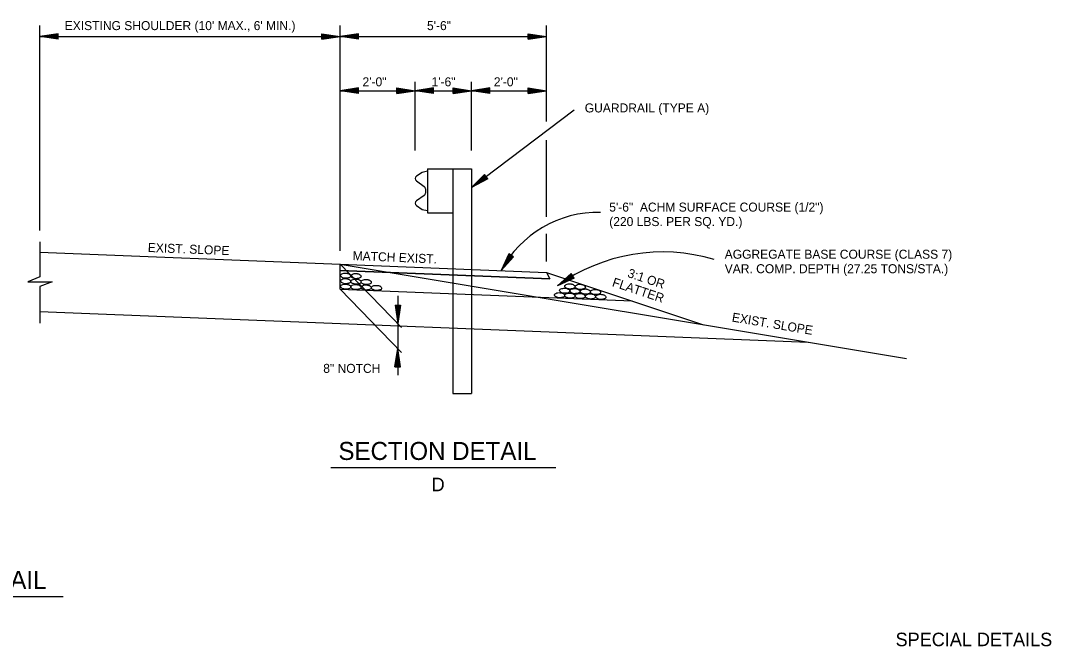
# Model space of a CAD drawing. Extents: x 1374136 to 1374281, y 380549 to 380948.
# Drawn here: x 1374212.2 to 1374280.9, y 380848.8 to 380890.4 of the extents above; entities that cross this region are included whole.
import ezdxf

# ---------------------------------------------------------------- set-up
doc = ezdxf.new("R2010")
doc.units = 0
for name, color, linetype in [('C-ANNO-TEXT', 7, 'Continuous'), ('Default', 7, 'Continuous'), ('G-ANNO-TEXT', 7, 'Continuous'), ('R_Draft', 7, 'Continuous')]:
    doc.layers.add(name, color=color, linetype=linetype)

msp = doc.modelspace()

# ---------------------------------------------------------------- linework, layer by layer
at = {"layer": 'C-ANNO-TEXT'}
msp.add_lwpolyline([(1374213.507, 380875.703), (1374213.507, 380873.373), (1374212.696, 380873.049), (1374214.318, 380873.049), (1374213.507, 380872.726), (1374213.507, 380870.301)], dxfattribs=at)
at = {"layer": 'Default'}
for p, q in [((1374213.507, 380876.461), (1374213.507, 380890.113)), ((1374214.724, 380889.571), (1374213.507, 380889.388)), ((1374214.724, 380889.54), (1374213.711, 380889.388)), ((1374214.724, 380889.508), (1374213.92, 380889.388)), ((1374214.725, 380889.204), (1374214.724, 380889.571)), ((1374232.29, 380889.571), (1374233.507, 380889.388)), ((1374232.29, 380889.204), (1374232.29, 380889.571)), ((1374232.29, 380889.54), (1374233.303, 380889.388)), ((1374232.29, 380889.508), (1374233.094, 380889.388)), ((1374233.507, 380875.114), (1374233.507, 380890.113)), ((1374234.724, 380889.571), (1374233.507, 380889.388)), ((1374234.724, 380889.54), (1374233.711, 380889.388)), ((1374234.724, 380889.508), (1374233.92, 380889.388)), ((1374234.725, 380889.204), (1374234.724, 380889.571)), ((1374246.04, 380889.571), (1374247.257, 380889.388)), ((1374246.04, 380889.204), (1374246.04, 380889.571)), ((1374246.04, 380889.54), (1374247.053, 380889.388)), ((1374246.04, 380889.508), (1374246.844, 380889.388)), ((1374247.257, 380883.73), (1374247.257, 380890.113)), ((1374213.507, 380889.388), (1374233.507, 380889.388)), ((1374214.725, 380889.204), (1374213.507, 380889.388)), ((1374214.725, 380889.236), (1374213.711, 380889.388)), ((1374214.725, 380889.267), (1374213.92, 380889.388)), ((1374214.724, 380889.479), (1374214.124, 380889.388)), ((1374214.725, 380889.297), (1374214.124, 380889.388)), ((1374214.724, 380889.447), (1374214.328, 380889.389)), ((1374214.725, 380889.328), (1374214.328, 380889.389)), ((1374214.725, 380889.416), (1374214.533, 380889.389)), ((1374214.725, 380889.36), (1374214.533, 380889.389)), ((1374232.29, 380889.479), (1374232.89, 380889.388)), ((1374232.29, 380889.447), (1374232.686, 380889.389)), ((1374232.29, 380889.416), (1374232.482, 380889.389)), ((1374232.29, 380889.328), (1374232.686, 380889.389)), ((1374232.29, 380889.36), (1374232.482, 380889.389)), ((1374232.29, 380889.204), (1374233.507, 380889.388)), ((1374232.29, 380889.267), (1374233.094, 380889.388)), ((1374232.29, 380889.236), (1374233.303, 380889.388)), ((1374232.29, 380889.297), (1374232.89, 380889.388)), ((1374233.507, 380889.388), (1374247.257, 380889.388)), ((1374234.725, 380889.204), (1374233.507, 380889.388)), ((1374234.725, 380889.236), (1374233.711, 380889.388)), ((1374234.725, 380889.267), (1374233.92, 380889.388)), ((1374234.724, 380889.479), (1374234.124, 380889.388)), ((1374234.725, 380889.297), (1374234.124, 380889.388)), ((1374234.724, 380889.447), (1374234.328, 380889.389)), ((1374234.725, 380889.328), (1374234.328, 380889.389)), ((1374234.725, 380889.416), (1374234.533, 380889.389)), ((1374234.725, 380889.36), (1374234.533, 380889.389)), ((1374246.04, 380889.479), (1374246.64, 380889.388)), ((1374246.04, 380889.447), (1374246.436, 380889.389)), ((1374246.04, 380889.416), (1374246.232, 380889.389)), ((1374246.04, 380889.328), (1374246.436, 380889.389)), ((1374246.04, 380889.36), (1374246.232, 380889.389)), ((1374246.04, 380889.204), (1374247.257, 380889.388)), ((1374246.04, 380889.267), (1374246.844, 380889.388)), ((1374246.04, 380889.236), (1374247.053, 380889.388)), ((1374246.04, 380889.297), (1374246.64, 380889.388)), ((1374238.507, 380881.787), (1374238.507, 380886.369)), ((1374242.257, 380881.787), (1374242.257, 380886.369)), ((1374234.724, 380885.96), (1374233.507, 380885.777)), ((1374233.507, 380885.777), (1374238.507, 380885.777)), ((1374234.725, 380885.593), (1374233.507, 380885.777)), ((1374234.724, 380885.929), (1374233.711, 380885.777)), ((1374234.725, 380885.625), (1374233.711, 380885.777)), ((1374234.724, 380885.897), (1374233.92, 380885.777)), ((1374234.725, 380885.656), (1374233.92, 380885.777)), ((1374234.724, 380885.868), (1374234.124, 380885.777)), ((1374234.725, 380885.686), (1374234.124, 380885.777)), ((1374234.724, 380885.836), (1374234.328, 380885.778)), ((1374234.725, 380885.717), (1374234.328, 380885.778)), ((1374234.725, 380885.805), (1374234.533, 380885.778)), ((1374234.725, 380885.749), (1374234.533, 380885.778)), ((1374234.725, 380885.593), (1374234.724, 380885.96)), ((1374237.29, 380885.96), (1374238.507, 380885.777)), ((1374237.29, 380885.593), (1374237.29, 380885.96)), ((1374237.29, 380885.929), (1374238.303, 380885.777)), ((1374237.29, 380885.897), (1374238.094, 380885.777)), ((1374237.29, 380885.868), (1374237.89, 380885.777)), ((1374237.29, 380885.836), (1374237.686, 380885.778)), ((1374237.29, 380885.805), (1374237.482, 380885.778)), ((1374237.29, 380885.717), (1374237.686, 380885.778)), ((1374237.29, 380885.749), (1374237.482, 380885.778)), ((1374237.29, 380885.593), (1374238.507, 380885.777)), ((1374237.29, 380885.656), (1374238.094, 380885.777)), ((1374237.29, 380885.625), (1374238.303, 380885.777)), ((1374237.29, 380885.686), (1374237.89, 380885.777)), ((1374239.724, 380885.96), (1374238.507, 380885.777)), ((1374238.507, 380885.777), (1374242.257, 380885.777)), ((1374239.725, 380885.593), (1374238.507, 380885.777)), ((1374239.724, 380885.929), (1374238.711, 380885.777)), ((1374239.725, 380885.625), (1374238.711, 380885.777)), ((1374239.724, 380885.897), (1374238.92, 380885.777)), ((1374239.725, 380885.656), (1374238.92, 380885.777)), ((1374239.724, 380885.868), (1374239.124, 380885.777)), ((1374239.725, 380885.686), (1374239.124, 380885.777)), ((1374239.724, 380885.836), (1374239.328, 380885.778)), ((1374239.725, 380885.717), (1374239.328, 380885.778)), ((1374239.725, 380885.805), (1374239.533, 380885.778)), ((1374239.725, 380885.749), (1374239.533, 380885.778)), ((1374239.725, 380885.593), (1374239.724, 380885.96)), ((1374241.04, 380885.96), (1374242.257, 380885.777)), ((1374241.04, 380885.593), (1374241.04, 380885.96)), ((1374241.04, 380885.929), (1374242.053, 380885.777)), ((1374241.04, 380885.897), (1374241.844, 380885.777)), ((1374241.04, 380885.868), (1374241.64, 380885.777)), ((1374241.04, 380885.836), (1374241.436, 380885.778)), ((1374241.04, 380885.805), (1374241.232, 380885.778)), ((1374241.04, 380885.717), (1374241.436, 380885.778)), ((1374241.04, 380885.749), (1374241.232, 380885.778)), ((1374241.04, 380885.593), (1374242.257, 380885.777)), ((1374241.04, 380885.656), (1374241.844, 380885.777)), ((1374241.04, 380885.625), (1374242.053, 380885.777)), ((1374241.04, 380885.686), (1374241.64, 380885.777)), ((1374243.474, 380885.96), (1374242.257, 380885.777)), ((1374242.257, 380885.777), (1374247.257, 380885.777)), ((1374243.475, 380885.593), (1374242.257, 380885.777)), ((1374243.474, 380885.929), (1374242.461, 380885.777)), ((1374243.475, 380885.625), (1374242.461, 380885.777)), ((1374243.474, 380885.897), (1374242.67, 380885.777)), ((1374243.475, 380885.656), (1374242.67, 380885.777)), ((1374243.474, 380885.868), (1374242.874, 380885.777)), ((1374243.475, 380885.686), (1374242.874, 380885.777)), ((1374243.474, 380885.836), (1374243.078, 380885.778)), ((1374243.475, 380885.717), (1374243.078, 380885.778)), ((1374243.475, 380885.805), (1374243.283, 380885.778)), ((1374243.475, 380885.749), (1374243.283, 380885.778)), ((1374243.475, 380885.593), (1374243.474, 380885.96)), ((1374246.04, 380885.96), (1374247.257, 380885.777)), ((1374246.04, 380885.593), (1374246.04, 380885.96)), ((1374246.04, 380885.929), (1374247.053, 380885.777)), ((1374246.04, 380885.897), (1374246.844, 380885.777)), ((1374246.04, 380885.868), (1374246.64, 380885.777)), ((1374246.04, 380885.836), (1374246.436, 380885.778)), ((1374246.04, 380885.805), (1374246.232, 380885.778)), ((1374246.04, 380885.717), (1374246.436, 380885.778)), ((1374246.04, 380885.749), (1374246.232, 380885.778)), ((1374246.04, 380885.593), (1374247.257, 380885.777)), ((1374246.04, 380885.656), (1374246.844, 380885.777)), ((1374246.04, 380885.625), (1374247.053, 380885.777)), ((1374246.04, 380885.686), (1374246.64, 380885.777)), ((1374242.257, 380879.324), (1374249.102, 380884.498)), ((1374247.257, 380877.376), (1374247.257, 380882.476)), ((1374239.332, 380880.564), (1374242.257, 380880.564)), ((1374239.332, 380880.564), (1374239.332, 380877.639)), ((1374241.007, 380880.564), (1374241.007, 380865.616)), ((1374242.257, 380880.564), (1374242.257, 380865.616)), ((1374238.969, 380880.336), (1374238.593, 380880.084)), ((1374239.332, 380880.406), (1374238.969, 380880.336)), ((1374243.119, 380880.202), (1374242.257, 380879.324)), ((1374243.337, 380879.914), (1374242.257, 380879.324)), ((1374243.14, 380880.18), (1374242.419, 380879.445)), ((1374243.322, 380879.936), (1374242.419, 380879.445)), ((1374243.16, 380880.151), (1374242.591, 380879.577)), ((1374243.299, 380879.962), (1374242.591, 380879.577)), ((1374243.173, 380880.127), (1374242.751, 380879.697)), ((1374243.281, 380879.987), (1374242.751, 380879.697)), ((1374243.193, 380880.106), (1374242.912, 380879.82)), ((1374243.26, 380880.013), (1374242.912, 380879.82)), ((1374243.211, 380880.08), (1374243.076, 380879.944)), ((1374243.247, 380880.04), (1374243.076, 380879.944)), ((1374243.337, 380879.914), (1374243.119, 380880.202)), ((1374238.59, 380879.763), (1374239.102, 380879.405)), ((1374239.184, 380879.246), (1374239.184, 380879.102)), ((1374239.102, 380878.799), (1374238.59, 380878.44)), ((1374239.184, 380879.102), (1374239.184, 380878.958)), ((1374238.593, 380878.12), (1374238.969, 380877.868)), ((1374238.969, 380877.868), (1374239.332, 380877.797)), ((1374239.332, 380877.639), (1374241.007, 380877.639)), ((1374247.257, 380874.406), (1374247.257, 380876.243)), ((1374213.507, 380875.024), (1374233.507, 380874.224)), ((1374244.742, 380874.916), (1374244.228, 380873.795)), ((1374245.047, 380874.714), (1374244.228, 380873.795)), ((1374244.765, 380874.895), (1374244.339, 380873.967)), ((1374245.024, 380874.733), (1374244.339, 380873.967)), ((1374244.793, 380874.879), (1374244.454, 380874.143)), ((1374244.993, 380874.746), (1374244.454, 380874.143)), ((1374244.817, 380874.863), (1374244.562, 380874.31)), ((1374244.969, 380874.765), (1374244.562, 380874.31)), ((1374244.845, 380874.847), (1374244.677, 380874.484)), ((1374244.944, 380874.781), (1374244.677, 380874.484)), ((1374245.047, 380874.714), (1374244.742, 380874.916)), ((1374244.873, 380874.828), (1374244.791, 380874.653)), ((1374244.918, 380874.799), (1374244.791, 380874.653)), ((1374237.596, 380870.005), (1374233.507, 380874.224)), ((1374233.507, 380874.224), (1374247.257, 380873.674)), ((1374233.507, 380874.224), (1374271.236, 380867.936)), ((1374233.507, 380872.549), (1374233.507, 380874.224)), ((1374233.507, 380873.799), (1374247.474, 380873.241)), ((1374247.257, 380873.674), (1374257.707, 380870.191)), ((1374247.257, 380873.674), (1374247.474, 380873.241)), ((1374248.905, 380873.599), (1374247.982, 380872.784)), ((1374249.105, 380873.29), (1374247.982, 380872.784)), ((1374248.923, 380873.571), (1374248.154, 380872.893)), ((1374249.086, 380873.316), (1374248.154, 380872.893)), ((1374248.939, 380873.545), (1374248.328, 380873.008)), ((1374249.068, 380873.342), (1374248.328, 380873.008)), ((1374248.955, 380873.521), (1374248.498, 380873.119)), ((1374249.052, 380873.365), (1374248.498, 380873.119)), ((1374248.971, 380873.493), (1374248.67, 380873.23)), ((1374249.036, 380873.391), (1374248.67, 380873.23)), ((1374248.989, 380873.467), (1374248.844, 380873.341)), ((1374249.02, 380873.42), (1374248.844, 380873.341)), ((1374249.105, 380873.29), (1374248.905, 380873.599)), ((1374237.596, 380868.33), (1374233.507, 380872.549)), ((1374233.507, 380872.549), (1374252.967, 380871.771)), ((1374237.339, 380872.105), (1374237.339, 380866.829)), ((1374213.507, 380871.074), (1374264.691, 380869.027)), ((1374237.163, 380871.488), (1374237.339, 380870.271)), ((1374237.163, 380871.488), (1374237.524, 380871.487)), ((1374237.19, 380871.489), (1374237.339, 380870.472)), ((1374237.224, 380871.487), (1374237.341, 380870.689)), ((1374237.255, 380871.487), (1374237.341, 380870.89)), ((1374237.288, 380871.487), (1374237.343, 380871.092)), ((1374237.318, 380871.492), (1374237.344, 380871.297)), ((1374237.494, 380871.49), (1374237.339, 380870.472)), ((1374237.524, 380871.487), (1374237.339, 380870.271)), ((1374237.459, 380871.489), (1374237.341, 380870.689)), ((1374237.431, 380871.485), (1374237.341, 380870.89)), ((1374237.403, 380871.488), (1374237.343, 380871.092)), ((1374237.372, 380871.487), (1374237.344, 380871.297)), ((1374237.156, 380867.379), (1374237.339, 380868.596)), ((1374237.183, 380867.378), (1374237.338, 380868.394)), ((1374237.487, 380867.375), (1374237.338, 380868.394)), ((1374237.518, 380867.378), (1374237.339, 380868.596)), ((1374237.218, 380867.38), (1374237.339, 380868.177)), ((1374237.249, 380867.379), (1374237.338, 380867.976)), ((1374237.282, 380867.38), (1374237.338, 380867.774)), ((1374237.311, 380867.374), (1374237.338, 380867.569)), ((1374237.425, 380867.381), (1374237.338, 380867.976)), ((1374237.397, 380867.377), (1374237.338, 380867.774)), ((1374237.365, 380867.379), (1374237.338, 380867.569)), ((1374237.452, 380867.376), (1374237.339, 380868.177)), ((1374237.156, 380867.379), (1374237.518, 380867.378)), ((1374232.89, 380860.679), (1374247.874, 380860.679)), ((1374191.594, 380852.092), (1374215.044, 380852.092))]:
    msp.add_line(p, q, dxfattribs=at)
msp.add_lwpolyline([(1374233.507, 380873.799), (1374233.507, 380874.224), (1374247.257, 380873.674), (1374247.474, 380873.241)], close=True, dxfattribs=at)
for centre, radius, start, end in [((1374238.702, 380879.923), 0.195, 124.15804, 234.74711), ((1374238.989, 380879.246), 0.195, 360, 54.74711), ((1374238.989, 380878.958), 0.195, 305.25289, 0), ((1374238.702, 380878.281), 0.195, 125.25289, 235.84196), ((1374250.7, 380870.331), 7.341, 88.82671, 151.84158), ((1374254.984, 380863.012), 12.021, 73.3815, 125.63175)]:
    msp.add_arc(centre, radius, start, end, dxfattribs=at)
for points in [[(1374233.879, 380873.622), (1374233.758, 380873.621), (1374233.612, 380873.572), (1374233.541, 380873.507), (1374233.53, 380873.464), (1374233.565, 380873.39), (1374233.608, 380873.357), (1374233.684, 380873.319), (1374233.804, 380873.285), (1374233.862, 380873.28), (1374233.954, 380873.286), (1374234.052, 380873.303), (1374234.129, 380873.331), (1374234.199, 380873.388), (1374234.211, 380873.431), (1374234.19, 380873.497), (1374234.136, 380873.542), (1374234.086, 380873.579), (1374234.006, 380873.606), (1374233.955, 380873.618), (1374233.879, 380873.622)], [(1374233.879, 380873.257), (1374233.758, 380873.256), (1374233.612, 380873.207), (1374233.541, 380873.142), (1374233.53, 380873.099), (1374233.565, 380873.025), (1374233.608, 380872.992), (1374233.684, 380872.954), (1374233.804, 380872.92), (1374233.862, 380872.915), (1374233.954, 380872.921), (1374234.052, 380872.938), (1374234.129, 380872.966), (1374234.199, 380873.023), (1374234.211, 380873.066), (1374234.19, 380873.132), (1374234.136, 380873.177), (1374234.086, 380873.214), (1374234.006, 380873.241), (1374233.955, 380873.253), (1374233.879, 380873.257)], [(1374234.565, 380873.595), (1374234.444, 380873.593), (1374234.298, 380873.544), (1374234.227, 380873.48), (1374234.216, 380873.436), (1374234.251, 380873.363), (1374234.294, 380873.329), (1374234.37, 380873.292), (1374234.49, 380873.257), (1374234.548, 380873.253), (1374234.64, 380873.258), (1374234.738, 380873.275), (1374234.815, 380873.303), (1374234.885, 380873.36), (1374234.897, 380873.404), (1374234.876, 380873.47), (1374234.822, 380873.514), (1374234.772, 380873.552), (1374234.692, 380873.578), (1374234.641, 380873.59), (1374234.565, 380873.595)], [(1374234.565, 380873.23), (1374234.444, 380873.228), (1374234.298, 380873.179), (1374234.227, 380873.115), (1374234.216, 380873.071), (1374234.251, 380872.998), (1374234.294, 380872.964), (1374234.37, 380872.927), (1374234.49, 380872.892), (1374234.548, 380872.888), (1374234.64, 380872.893), (1374234.738, 380872.91), (1374234.815, 380872.938), (1374234.885, 380872.995), (1374234.897, 380873.039), (1374234.876, 380873.105), (1374234.822, 380873.149), (1374234.772, 380873.187), (1374234.692, 380873.213), (1374234.641, 380873.225), (1374234.565, 380873.23)], [(1374235.251, 380873.203), (1374235.13, 380873.201), (1374234.984, 380873.152), (1374234.913, 380873.087), (1374234.902, 380873.044), (1374234.937, 380872.97), (1374234.98, 380872.937), (1374235.056, 380872.899), (1374235.176, 380872.865), (1374235.234, 380872.86), (1374235.326, 380872.866), (1374235.424, 380872.883), (1374235.501, 380872.911), (1374235.571, 380872.968), (1374235.583, 380873.011), (1374235.562, 380873.077), (1374235.508, 380873.122), (1374235.458, 380873.159), (1374235.378, 380873.186), (1374235.327, 380873.198), (1374235.251, 380873.203)], [(1374233.879, 380872.892), (1374233.758, 380872.891), (1374233.612, 380872.842), (1374233.541, 380872.777), (1374233.53, 380872.734), (1374233.565, 380872.66), (1374233.608, 380872.627), (1374233.684, 380872.589), (1374233.804, 380872.555), (1374233.862, 380872.55), (1374233.954, 380872.556), (1374234.052, 380872.573), (1374234.129, 380872.601), (1374234.199, 380872.658), (1374234.211, 380872.701), (1374234.19, 380872.767), (1374234.136, 380872.812), (1374234.086, 380872.849), (1374234.006, 380872.876), (1374233.955, 380872.888), (1374233.879, 380872.892)], [(1374234.565, 380872.865), (1374234.444, 380872.863), (1374234.298, 380872.814), (1374234.227, 380872.75), (1374234.216, 380872.706), (1374234.251, 380872.633), (1374234.294, 380872.599), (1374234.37, 380872.562), (1374234.49, 380872.527), (1374234.548, 380872.523), (1374234.64, 380872.528), (1374234.738, 380872.545), (1374234.815, 380872.573), (1374234.885, 380872.63), (1374234.897, 380872.674), (1374234.876, 380872.74), (1374234.822, 380872.784), (1374234.772, 380872.822), (1374234.692, 380872.848), (1374234.641, 380872.86), (1374234.565, 380872.865)], [(1374235.251, 380872.838), (1374235.13, 380872.836), (1374234.984, 380872.787), (1374234.913, 380872.722), (1374234.902, 380872.679), (1374234.937, 380872.605), (1374234.98, 380872.572), (1374235.056, 380872.534), (1374235.176, 380872.5), (1374235.234, 380872.495), (1374235.326, 380872.501), (1374235.424, 380872.518), (1374235.501, 380872.546), (1374235.571, 380872.603), (1374235.583, 380872.646), (1374235.562, 380872.712), (1374235.508, 380872.757), (1374235.458, 380872.794), (1374235.378, 380872.821), (1374235.327, 380872.833), (1374235.251, 380872.838)], [(1374235.937, 380872.81), (1374235.816, 380872.808), (1374235.67, 380872.76), (1374235.6, 380872.695), (1374235.588, 380872.651), (1374235.623, 380872.578), (1374235.666, 380872.544), (1374235.742, 380872.507), (1374235.862, 380872.472), (1374235.92, 380872.468), (1374236.012, 380872.474), (1374236.11, 380872.49), (1374236.187, 380872.518), (1374236.258, 380872.575), (1374236.269, 380872.619), (1374236.248, 380872.685), (1374236.194, 380872.73), (1374236.144, 380872.767), (1374236.064, 380872.794), (1374236.013, 380872.805), (1374235.937, 380872.81)], [(1374248.133, 380872.322), (1374248.013, 380872.32), (1374247.866, 380872.272), (1374247.796, 380872.207), (1374247.784, 380872.164), (1374247.82, 380872.09), (1374247.863, 380872.057), (1374247.939, 380872.019), (1374248.059, 380871.984), (1374248.117, 380871.98), (1374248.208, 380871.986), (1374248.307, 380872.002), (1374248.384, 380872.03), (1374248.454, 380872.088), (1374248.466, 380872.131), (1374248.445, 380872.197), (1374248.391, 380872.242), (1374248.34, 380872.279), (1374248.26, 380872.306), (1374248.21, 380872.317), (1374248.133, 380872.322)], [(1374248.478, 380872.623), (1374248.35, 380872.611), (1374248.207, 380872.577), (1374248.133, 380872.509), (1374248.122, 380872.469), (1374248.157, 380872.391), (1374248.2, 380872.358), (1374248.28, 380872.313), (1374248.396, 380872.282), (1374248.454, 380872.281), (1374248.546, 380872.287), (1374248.648, 380872.293), (1374248.725, 380872.328), (1374248.791, 380872.389), (1374248.803, 380872.436), (1374248.782, 380872.502), (1374248.728, 380872.547), (1374248.678, 380872.569), (1374248.598, 380872.603), (1374248.551, 380872.619), (1374248.478, 380872.623)], [(1374248.822, 380872.907), (1374248.702, 380872.905), (1374248.555, 380872.857), (1374248.485, 380872.792), (1374248.473, 380872.748), (1374248.509, 380872.675), (1374248.552, 380872.641), (1374248.628, 380872.604), (1374248.748, 380872.569), (1374248.806, 380872.565), (1374248.897, 380872.571), (1374248.996, 380872.587), (1374249.073, 380872.615), (1374249.143, 380872.672), (1374249.154, 380872.716), (1374249.134, 380872.782), (1374249.08, 380872.827), (1374249.029, 380872.864), (1374248.949, 380872.891), (1374248.899, 380872.902), (1374248.822, 380872.907)], [(1374249.164, 380872.596), (1374249.036, 380872.583), (1374248.893, 380872.549), (1374248.819, 380872.481), (1374248.808, 380872.441), (1374248.843, 380872.364), (1374248.886, 380872.331), (1374248.966, 380872.286), (1374249.082, 380872.255), (1374249.14, 380872.254), (1374249.232, 380872.26), (1374249.334, 380872.265), (1374249.411, 380872.301), (1374249.477, 380872.362), (1374249.489, 380872.409), (1374249.468, 380872.475), (1374249.414, 380872.519), (1374249.364, 380872.542), (1374249.284, 380872.576), (1374249.237, 380872.591), (1374249.164, 380872.596)], [(1374249.508, 380872.88), (1374249.388, 380872.878), (1374249.241, 380872.829), (1374249.171, 380872.765), (1374249.159, 380872.721), (1374249.195, 380872.648), (1374249.238, 380872.614), (1374249.314, 380872.576), (1374249.434, 380872.542), (1374249.492, 380872.537), (1374249.583, 380872.543), (1374249.682, 380872.56), (1374249.759, 380872.588), (1374249.829, 380872.645), (1374249.841, 380872.689), (1374249.82, 380872.754), (1374249.766, 380872.799), (1374249.715, 380872.836), (1374249.635, 380872.863), (1374249.585, 380872.875), (1374249.508, 380872.88)], [(1374249.85, 380872.569), (1374249.722, 380872.556), (1374249.579, 380872.522), (1374249.506, 380872.454), (1374249.494, 380872.414), (1374249.529, 380872.337), (1374249.572, 380872.303), (1374249.652, 380872.258), (1374249.768, 380872.227), (1374249.826, 380872.226), (1374249.918, 380872.232), (1374250.02, 380872.238), (1374250.097, 380872.273), (1374250.163, 380872.334), (1374250.175, 380872.381), (1374250.154, 380872.447), (1374250.1, 380872.492), (1374250.05, 380872.514), (1374249.97, 380872.549), (1374249.923, 380872.564), (1374249.85, 380872.569)], [(1374250.536, 380872.541), (1374250.408, 380872.529), (1374250.266, 380872.494), (1374250.192, 380872.426), (1374250.18, 380872.386), (1374250.215, 380872.309), (1374250.259, 380872.276), (1374250.338, 380872.231), (1374250.454, 380872.2), (1374250.512, 380872.199), (1374250.604, 380872.205), (1374250.706, 380872.21), (1374250.783, 380872.246), (1374250.85, 380872.307), (1374250.861, 380872.354), (1374250.84, 380872.42), (1374250.786, 380872.464), (1374250.736, 380872.487), (1374250.656, 380872.521), (1374250.609, 380872.536), (1374250.536, 380872.541)], [(1374248.819, 380872.295), (1374248.699, 380872.293), (1374248.552, 380872.244), (1374248.482, 380872.18), (1374248.47, 380872.136), (1374248.506, 380872.063), (1374248.549, 380872.029), (1374248.625, 380871.992), (1374248.745, 380871.957), (1374248.803, 380871.952), (1374248.894, 380871.958), (1374248.993, 380871.975), (1374249.07, 380872.003), (1374249.14, 380872.06), (1374249.152, 380872.104), (1374249.131, 380872.17), (1374249.077, 380872.214), (1374249.026, 380872.251), (1374248.946, 380872.278), (1374248.896, 380872.29), (1374248.819, 380872.295)], [(1374249.505, 380872.267), (1374249.385, 380872.266), (1374249.238, 380872.217), (1374249.168, 380872.152), (1374249.156, 380872.109), (1374249.192, 380872.035), (1374249.235, 380872.002), (1374249.311, 380871.964), (1374249.431, 380871.929), (1374249.489, 380871.925), (1374249.58, 380871.931), (1374249.679, 380871.947), (1374249.756, 380871.975), (1374249.826, 380872.033), (1374249.838, 380872.076), (1374249.817, 380872.142), (1374249.763, 380872.187), (1374249.712, 380872.224), (1374249.633, 380872.251), (1374249.582, 380872.263), (1374249.505, 380872.267)], [(1374250.191, 380872.24), (1374250.071, 380872.238), (1374249.924, 380872.189), (1374249.854, 380872.125), (1374249.842, 380872.081), (1374249.878, 380872.008), (1374249.921, 380871.974), (1374249.997, 380871.937), (1374250.117, 380871.902), (1374250.175, 380871.897), (1374250.266, 380871.903), (1374250.365, 380871.92), (1374250.442, 380871.948), (1374250.512, 380872.005), (1374250.524, 380872.049), (1374250.503, 380872.115), (1374250.449, 380872.159), (1374250.398, 380872.197), (1374250.319, 380872.223), (1374250.268, 380872.235), (1374250.191, 380872.24)], [(1374250.877, 380872.212), (1374250.757, 380872.211), (1374250.61, 380872.162), (1374250.54, 380872.097), (1374250.529, 380872.054), (1374250.564, 380871.98), (1374250.607, 380871.947), (1374250.683, 380871.909), (1374250.803, 380871.875), (1374250.861, 380871.87), (1374250.952, 380871.876), (1374251.051, 380871.893), (1374251.128, 380871.921), (1374251.198, 380871.978), (1374251.21, 380872.021), (1374251.189, 380872.087), (1374251.135, 380872.132), (1374251.084, 380872.169), (1374251.005, 380872.196), (1374250.954, 380872.208), (1374250.877, 380872.212)]]:
    msp.add_spline(points, degree=3, dxfattribs=at)
at = {"layer": 'R_Draft'}
msp.add_line((1374241.007, 380865.616), (1374242.257, 380865.616), dxfattribs=at)

# ---------------------------------------------------------------- texts
at = {"layer": 'Default'}
for s, height, p in [("EXISTING SHOULDER (10' MAX., 6' MIN.)", 0.6, (1374215.154, 380889.813)), ('5\'-6"', 0.6, (1374239.293, 380889.813)), ('2\'-0"', 0.6, (1374234.996, 380886.069)), ('1\'-6"', 0.6, (1374239.594, 380886.069)), ('2\'-0"', 0.6, (1374243.746, 380886.069)), ('GUARDRAIL (TYPE A)', 0.6, (1374249.802, 380884.33)), ('5\'-6"  ACHM SURFACE COURSE (1/2")', 0.6, (1374251.433, 380877.723)), ('(220 LBS. PER SQ. YD.)', 0.6, (1374251.433, 380876.759)), ('AGGREGATE BASE COURSE (CLASS 7)', 0.6, (1374259.125, 380874.583)), ('VAR. COMP. DEPTH (27.25 TONS/STA.)', 0.6, (1374259.125, 380873.618)), ('8" NOTCH', 0.6, (1374232.379, 380866.98)), ('SECTION DETAIL', 1.2, (1374233.39, 380861.179)), ('D', 0.9, (1374239.602, 380859.095)), ('WIDENING FOR GUARDRAIL', 1.2, (1374192.094, 380852.592))]:
    msp.add_text(s, height=height, dxfattribs=at).set_placement(p)
for s, rotation, p in [('EXIST. SLOPE', 357.70939, (1374220.682, 380875.037)), ('MATCH EXIST.', 357.70939, (1374234.328, 380874.492)), ('3:1 OR', 341.56505, (1374252.609, 380873.378)), ('FLATTER', 341.56505, (1374251.585, 380872.77)), ('EXIST. SLOPE', 350.53768, (1374259.574, 380870.406))]:
    msp.add_text(s, height=0.6, rotation=rotation, dxfattribs=at).set_placement(p)
at = {"layer": 'G-ANNO-TEXT'}
msp.add_text('SPECIAL DETAILS', height=0.9, dxfattribs=at).set_placement((1374270.512, 380848.773))

doc.saveas('drawing.dxf')
